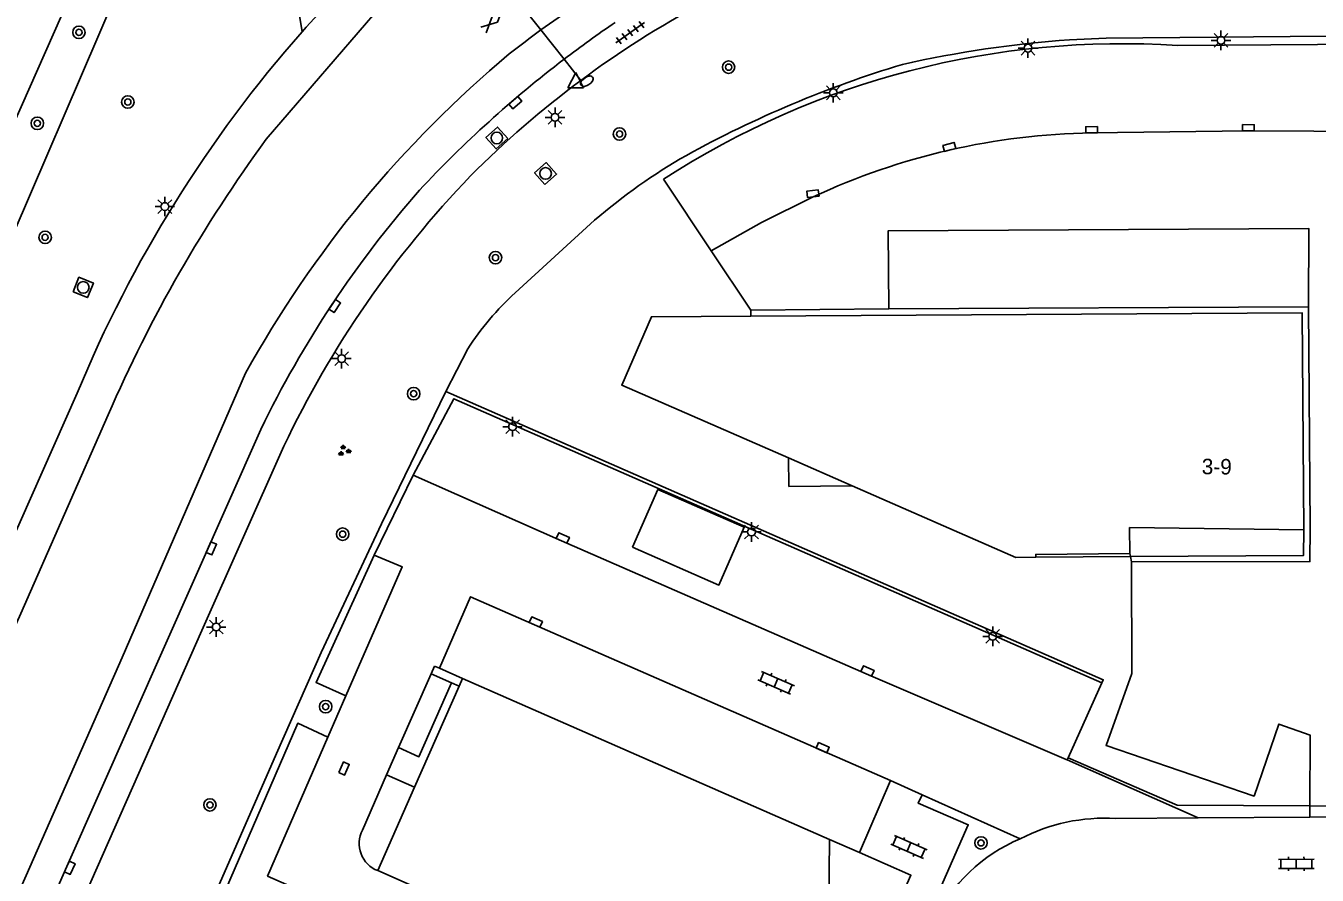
# Model space of a CAD drawing. Extents: x 131000 to 133013, y 393000 to 396501.
# Drawn here: x 131810.6 to 131893.7, y 394917.7 to 394972.4 of the extents above; entities that cross this region are included whole.
import ezdxf

# ---------------------------------------------------------------- set-up
doc = ezdxf.new("R2010")
doc.units = 0
for name, color, linetype in [('gg-afsc-hekwerk', 7, 'Continuous'), ('gg-afsc-muur', 7, 'Continuous'), ('gg-anno-huisnummerreeks BGT', 7, 'Continuous'), ('gg-bbg-hoofdgebouw', 7, 'Continuous'), ('gg-bbg-onder overbouw', 7, 'Continuous'), ('gg-bbg-pand overbouw', 7, 'Continuous'), ('gg-knt-verharding', 7, 'Continuous'), ('gg-knt-verharding nz', 7, 'Continuous'), ('gt-grn-groengrens', 7, 'Continuous'), ('gt-grn-vlakafsluiter', 7, 'Continuous'), ('gt-grn-weggrens', 7, 'Continuous'), ('gt-symb-boom', 7, 'Continuous'), ('gt-symb-brandkraan', 7, 'Continuous'), ('gt-symb-gesloten verharding', 7, 'Continuous'), ('gt-symb-groenvak', 7, 'Continuous'), ('gt-symb-klinker verharding', 7, 'Continuous'), ('gt-symb-kolk', 7, 'Continuous'), ('gt-symb-kolk center center', 7, 'Continuous'), ('gt-symb-lichtmast', 7, 'Continuous'), ('gt-symb-rioolschacht', 7, 'Continuous'), ('gt-symb-tegel verharding', 7, 'Continuous'), ('gt-symb-waterafsluiter', 7, 'Continuous')]:
    doc.layers.add(name, color=color, linetype=linetype)

# ---------------------------------------------------------------- blocks, each defined once
blk = doc.blocks.new('gt0-LMAST')
at = {"layer": 'gt-symb-lichtmast'}
for p, q in [((-0.182, 0.173), (-0.447, 0.438)), ((-0.005, 0.246), (-0.005, 0.621)), ((0.172, 0.173), (0.437, 0.438)), ((-0.255, -0.004), (-0.63, -0.004)), ((-0.182, -0.181), (-0.447, -0.446)), ((-0.005, -0.254), (-0.005, -0.629)), ((0.437, -0.446), (0.172, -0.181)), ((0.245, -0.004), (0.62, -0.004))]:
    blk.add_line(p, q, dxfattribs=at)
blk.add_circle((-0.005, -0.004), 0.25, dxfattribs=at)
blk = doc.blocks.new('gt0-TEG1')
at = {"layer": 'gt-symb-tegel verharding'}
for p, q in [((-1.125, 0), (1.125, 0)), ((-0.9, -0.25), (-0.9, 0.25)), ((-0.45, -0.25), (-0.45, 0.25)), ((0, -0.25), (0, 0.25)), ((0.45, -0.25), (0.45, 0.25)), ((0.9, -0.25), (0.9, 0.25))]:
    blk.add_line(p, q, dxfattribs=at)
blk = doc.blocks.new('gt0-BOOM')
at = {"layer": 'gt-symb-boom'}
for radius in [0.4, 0.2]:
    blk.add_circle((0, 0), radius, dxfattribs=at)
blk = doc.blocks.new('gt0-GESVH1')
at = {"layer": 'gt-symb-gesloten verharding'}
for p, q in [((-0.992, -0.261), (0.008, 0.239)), ((0.008, -0.261), (-0.992, 0.239)), ((0.008, 0.239), (1.008, -0.261)), ((1.008, 0.239), (0.008, -0.261))]:
    blk.add_line(p, q, dxfattribs=at)
blk = doc.blocks.new('gt0-KOLK')
at = {"layer": 'gt-symb-kolk'}
blk.add_lwpolyline([(0, 0), (0.375, 0), (0.375, 0.4), (-0.375, 0.4), (-0.375, 0), (0, 0)], dxfattribs=at)
blk = doc.blocks.new('gt0-RS')
at = {"layer": 'gt-symb-rioolschacht'}
blk.add_lwpolyline([(-0.5, -0.5), (0.5, -0.5), (0.5, 0.5), (-0.5, 0.5)], close=True, dxfattribs=at)
blk.add_circle((0, 0), 0.375, dxfattribs=at)
blk = doc.blocks.new('gt0-WAFSL')
at = {"layer": 'gt-symb-waterafsluiter'}
for p, q in [((-0.5, -0.333), (0, 0.667)), ((0, 0.667), (0.5, -0.333)), ((0.5, -0.333), (-0.5, -0.333))]:
    blk.add_line(p, q, dxfattribs=at)
blk = doc.blocks.new('gt0-BR')
at = {"layer": 'gt-symb-brandkraan'}
for centre, radius, start, end in [((-0.244, 0), 0.206, 107.56694, 252.43307), ((0.599, -2.664), 3, 106.89205, 107.56694), ((0, -0.691), 0.938, 73.10799, 106.89205), ((-0.599, -2.664), 3, 72.43309, 73.10799), ((0.244, 0), 0.206, 287.56695, 72.43309), ((0.599, 2.664), 3, 252.43307, 253.10797), ((0, 0.691), 0.938, 253.10797, 286.89206), ((-0.599, 2.664), 3, 286.89206, 287.56695)]:
    blk.add_arc(centre, radius, start, end, dxfattribs=at)
blk = doc.blocks.new('gt0-KL1')
at = {"layer": 'gt-symb-klinker verharding'}
for p, q in [((-1.15, 0.3), (1.15, 0.3)), ((-1, -0.3), (-1, 0.3)), ((-0.5, 0.3), (-0.5, 0.45)), ((0, -0.3), (0, 0.3)), ((0.5, 0.3), (0.5, 0.45)), ((1, -0.3), (1, 0.3)), ((-1.15, -0.3), (1.15, -0.3)), ((-0.5, -0.45), (-0.5, -0.3)), ((0.5, -0.45), (0.5, -0.3))]:
    blk.add_line(p, q, dxfattribs=at)
blk = doc.blocks.new('gt0-KOLKCC')
at = {"layer": 'gt-symb-kolk center center'}
blk.add_lwpolyline([(-0.375, 0.2), (0.375, 0.2), (0.375, -0.2), (-0.375, -0.2)], close=True, dxfattribs=at)
blk = doc.blocks.new('gt0-GRVAK')
at = {"layer": 'gt-symb-groenvak'}
for p, q in [((-0.11, 0.189), (-0.228, 0.24)), ((-0.182, 0.153), (0.088, 0.153)), ((-0.091, 0.211), (-0.156, 0.322)), ((-0.047, 0.214), (-0.047, 0.393)), ((-0.004, 0.211), (0.061, 0.322)), ((0.015, 0.189), (0.133, 0.24)), ((0.262, -0.052), (0.197, 0.059)), ((0.305, -0.049), (0.305, 0.13)), ((0.349, -0.052), (0.414, 0.059)), ((-0.245, -0.228), (-0.363, -0.177)), ((-0.318, -0.264), (-0.047, -0.264)), ((-0.226, -0.206), (-0.291, -0.095)), ((-0.183, -0.203), (-0.183, -0.024)), ((-0.139, -0.206), (-0.074, -0.095)), ((-0.12, -0.228), (-0.002, -0.177)), ((0.243, -0.074), (0.125, -0.023)), ((0.17, -0.11), (0.441, -0.11)), ((0.368, -0.074), (0.486, -0.023))]:
    blk.add_line(p, q, dxfattribs=at)

msp = doc.modelspace()

# ---------------------------------------------------------------- linework, layer by layer
at = {"layer": 'gg-afsc-hekwerk'}
for p, q in [((131847.171, 394959.864), (131842.065, 394955.195)), ((131837.604, 394948.848), (131839.008, 394951.577)), ((131877.655, 394925.264), (131879.819, 394930.082)), ((131897.868, 394922.132), (131893.202, 394922.16))]:
    msp.add_line(p, q, dxfattribs=at)
for points in [[(131903.78, 394971.81), (131880.092, 394971.597), (131877.743, 394971.48)], [(131837.604, 394948.848), (131833.448, 394940.313), (131829.566, 394932.029), (131826.705, 394925.539), (131822.874, 394916.809), (131823.026, 394916.543), (131808.751, 394884.954)], [(131879.819, 394930.082), (131879.911, 394930.286), (131837.604, 394948.848)], [(131849.604, 394938.812), (131855.169, 394936.378), (131856.799, 394940.103), (131851.234, 394942.538), (131849.604, 394938.812)], [(131893.202, 394922.16), (131884.654, 394922.21), (131877.655, 394925.264)]]:
    msp.add_lwpolyline(points, dxfattribs=at)
for centre, radius, start, end in [((131882.837, 394899.326), 72.333, 94.03832, 102.66003), ((131888.123, 394900.29), 72.75, 106.89239, 118.79886), ((131872.109, 394930.875), 38.239, 119.84825, 130.70416), ((131854.361, 394941.705), 18.253, 132.34914, 147.25913)]:
    msp.add_arc(centre, radius, start, end, dxfattribs=at)
at = {"layer": 'gg-afsc-muur'}
for p, q in [((131836.871, 394931.161), (131836.663, 394930.652)), ((131836.871, 394931.161), (131837.183, 394931.021)), ((131836.663, 394930.652), (131837.956, 394930.086)), ((131837.183, 394931.021), (131838.663, 394930.355)), ((131837.956, 394930.086), (131838.449, 394929.87))]:
    msp.add_line(p, q, dxfattribs=at)
at = {"layer": 'gg-bbg-hoofdgebouw'}
for p, q in [((131838.663, 394930.355), (131838.449, 394929.87)), ((131862.294, 394919.995), (131838.663, 394930.355)), ((131838.449, 394929.87), (131835.587, 394923.372)), ((131835.587, 394923.372), (131833.218, 394917.992)), ((131833.218, 394917.992), (131862.333, 394905.215))]:
    msp.add_line(p, q, dxfattribs=at)
for points in [[(131859.642, 394944.561), (131848.918, 394949.254), (131850.831, 394953.657), (131857.228, 394953.694)], [(131857.228, 394953.694), (131892.715, 394953.902), (131892.805, 394939.932)], [(131875.561, 394938.173), (131874.27, 394938.162), (131863.746, 394942.765)]]:
    msp.add_lwpolyline(points, dxfattribs=at)
at = {"layer": 'gg-bbg-onder overbouw'}
for p, q in [((131863.746, 394942.765), (131859.642, 394944.561)), ((131862.294, 394919.995), (131862.202, 394911.141))]:
    msp.add_line(p, q, dxfattribs=at)
for points in [[(131892.805, 394939.932), (131881.603, 394940.075), (131881.608, 394938.408)], [(131881.608, 394938.408), (131875.564, 394938.354), (131875.561, 394938.173)]]:
    msp.add_lwpolyline(points, dxfattribs=at)
at = {"layer": 'gg-bbg-pand overbouw'}
for p, q in [((131875.561, 394938.173), (131881.653, 394938.212)), ((131864.216, 394919.152), (131862.294, 394919.995))]:
    msp.add_line(p, q, dxfattribs=at)
for points in [[(131863.746, 394942.765), (131859.674, 394942.729), (131859.642, 394944.561)], [(131881.653, 394938.212), (131892.798, 394938.284), (131892.805, 394939.932)], [(131864.425, 394910.635), (131867.527, 394917.7), (131864.216, 394919.152)]]:
    msp.add_lwpolyline(points, dxfattribs=at)
at = {"layer": 'gg-knt-verharding'}
for p, q in [((131799.343, 394942.554), (131817.322, 394983.075)), ((131854.668, 394957.892), (131851.612, 394962.513)), ((131857.226, 394954.082), (131854.668, 394957.892)), ((131866.109, 394954.16), (131857.226, 394954.082)), ((131893.12, 394954.298), (131866.109, 394954.16)), ((131807.785, 394935.011), (131813.879, 394948.731)), ((131835.501, 394943.451), (131832.99, 394938.313)), ((131881.731, 394937.878), (131881.653, 394938.212)), ((131836.663, 394930.652), (131834.552, 394925.922)), ((131831.156, 394929.252), (131830.009, 394926.589)), ((131833.789, 394924.162), (131834.552, 394925.922)), ((131877.589, 394925.117), (131877.509, 394925.153)), ((131877.655, 394925.264), (131877.589, 394925.117)), ((131886.023, 394921.383), (131877.589, 394925.117)), ((131833.789, 394924.162), (131832.23, 394920.606)), ((131835.587, 394923.372), (131833.789, 394924.162)), ((131866.208, 394923.79), (131864.216, 394919.152)), ((131868.253, 394922.879), (131866.208, 394923.79)), ((131874.568, 394920.037), (131868.253, 394922.879)), ((131893.202, 394922.16), (131893.198, 394921.433)), ((131886.023, 394921.383), (131880.706, 394921.348)), ((131893.198, 394921.433), (131886.023, 394921.383)), ((131893.198, 394921.433), (131897.888, 394921.481))]:
    msp.add_line(p, q, dxfattribs=at)
for points in [[(131825.488, 394979.091), (131827.72, 394975.961), (131828.353, 394972.005)], [(131884.697, 394971.113), (131902.679, 394971.249), (131902.848, 394923.577), (131897.824, 394923.515)], [(131881.731, 394937.878), (131893.206, 394937.891), (131893.222, 394940.062), (131893.12, 394954.298)], [(131879.819, 394930.082), (131838.116, 394948.372), (131835.501, 394943.451)], [(131825.69, 394946.403), (131813.219, 394918.254), (131800.285, 394888.961), (131791.639, 394869.234), (131782.976, 394849.54), (131781.85, 394846.843)], [(131811.436, 394909.735), (131821.907, 394933.452), (131827.18, 394945.316)], [(131832.99, 394938.313), (131829.246, 394930.11), (131831.156, 394929.252)], [(131881.731, 394937.878), (131881.74, 394930.685), (131880.089, 394926.038), (131889.612, 394922.796), (131891.202, 394927.422), (131893.229, 394926.707), (131893.202, 394922.16)], [(131834.552, 394925.922), (131835.871, 394925.326), (131837.956, 394930.086)], [(131830.009, 394926.589), (131828.074, 394927.478), (131823.42, 394916.74), (131826.985, 394915.22), (131862.405, 394899.633)], [(131868.253, 394922.879), (131868.004, 394922.331), (131871.215, 394920.946), (131867.57, 394912.629), (131868.052, 394912.425)]]:
    msp.add_lwpolyline(points, dxfattribs=at)
for centre, radius, start, end in [((131877.006, 394928.516), 65.256, 127.50922, 138.20768), ((131883.562, 394918.66), 62.537, 109.66743, 126.59253), ((131890.633, 394917.136), 83.002, 138.61956, 157.62584), ((131890.439, 394910.916), 74.592, 124.20639, 127.32793), ((131881.107, 394916.983), 54.249, 86.20588, 122.93574), ((131890.234, 394911.222), 74.225, 127.34568, 137.05194), ((131883.618, 394918.602), 62.616, 126.60182, 135.20174), ((131886.981, 394916.911), 66.205, 136.21437, 154.59274), ((131887.586, 394916.411), 68.78, 138.71327, 154.14747), ((131879.989, 394909.678), 11.692, 86.48652, 117.62649), ((131833.898, 394919.743), 1.878, 152.63393, 248.77573), ((131878.498, 394910.436), 10.374, 112.26164, 155.71264)]:
    msp.add_arc(centre, radius, start, end, dxfattribs=at)
at = {"layer": 'gg-knt-verharding nz'}
msp.add_line((131881.653, 394938.212), (131881.608, 394938.408), dxfattribs=at)
for points in [[(131826.046, 394965.08), (131833.434, 394973.659), (131839.019, 394978.069)], [(131897.824, 394923.515), (131897.683, 394965.579), (131889.241, 394965.618), (131879.155, 394965.49)], [(131861.243, 394961.374), (131857.912, 394959.715), (131854.668, 394957.892)], [(131866.109, 394954.16), (131866.066, 394959.189), (131893.131, 394959.344), (131893.12, 394954.298)], [(131780.795, 394850.018), (131782.267, 394853.403), (131816.767, 394931.714), (131824.71, 394950.01)], [(131815.875, 394947.336), (131810.244, 394934.536), (131808.945, 394931.623), (131770.367, 394843.592), (131767.437, 394837.1)], [(131835.501, 394943.451), (131845.047, 394939.229), (131864.65, 394930.667), (131877.509, 394925.153)], [(131831.156, 394929.252), (131834.791, 394937.543), (131832.99, 394938.313)], [(131866.208, 394923.79), (131839.187, 394935.625), (131837.183, 394931.021)], [(131863.19, 394901.369), (131826.128, 394917.644), (131830.009, 394926.589)]]:
    msp.add_lwpolyline(points, dxfattribs=at)
for centre, radius, start, end in [((131883.725, 394917.197), 67.944, 89.86947, 126.07174), ((131884.168, 394916.637), 68.657, 126.09472, 128.22789), ((131888.222, 394914.867), 72.587, 129.87794, 151.04306), ((131879.843, 394921.464), 44.031, 90.89511, 114.98757), ((131899.831, 394910.999), 91.483, 143.76024, 156.59641)]:
    msp.add_arc(centre, radius, start, end, dxfattribs=at)
at = {"layer": 'gt-grn-groengrens'}
msp.add_line((131800.809, 394938.166), (131819.562, 394981.824), dxfattribs=at)
at = {"layer": 'gt-grn-vlakafsluiter'}
msp.add_line((131857.228, 394953.694), (131857.226, 394954.082), dxfattribs=at)
at = {"layer": 'gt-grn-weggrens'}
for p, q in [((131839.019, 394978.069), (131843.72, 394972.115)), ((131843.72, 394972.115), (131845.208, 394970.23)), ((131845.208, 394970.23), (131846.283, 394968.87))]:
    msp.add_line(p, q, dxfattribs=at)

# ---------------------------------------------------------------- block references
at = {"layer": 'gt-symb-boom'}
for p in [(131813.987, 394971.962), (131855.796, 394969.719), (131817.133, 394967.475), (131811.307, 394966.105), (131848.777, 394965.417), (131811.812, 394958.764), (131840.795, 394957.458), (131835.525, 394948.698), (131830.957, 394939.653), (131829.862, 394928.55), (131822.417, 394922.224), (131872.036, 394919.778)]:
    msp.add_blockref('gt0-BOOM', p, dxfattribs=at)
at = {"layer": 'gt-symb-brandkraan', "rotation": -145.80135638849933}
msp.add_blockref('gt0-BR', (131846.673, 394968.815), dxfattribs=at)
at = {"layer": 'gt-symb-gesloten verharding', "rotation": 43.298645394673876}
msp.add_blockref('gt0-GESVH1', (131840.73, 394972.804), dxfattribs=at)
at = {"layer": 'gt-symb-groenvak'}
msp.add_blockref('gt0-GRVAK', (131831.04, 394945.022), dxfattribs=at)
at = {"layer": 'gt-symb-klinker verharding'}
for p, rotation in [((131858.854, 394930.085), -23.642501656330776), ((131867.402, 394919.519), -23.642501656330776), ((131892.327, 394918.428), -179.54164354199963)]:
    msp.add_blockref('gt0-KL1', p, dxfattribs=dict(at, rotation=rotation))
at = {"layer": 'gt-symb-kolk'}
for p, rotation in [((131841.938, 394967.585), -139.38006045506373), ((131879.155, 394965.49), 0.2864765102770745), ((131889.241, 394965.618), -0.2864765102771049), ((131870.047, 394964.392), 14.772723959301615), ((131861.243, 394961.374), 6.60603415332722), ((131830.284, 394954.452), -123.57881372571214), ((131845.047, 394939.229), -23.82289949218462), ((131822.33, 394938.827), -113.8984778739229), ((131843.306, 394933.812), -23.642501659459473), ((131864.65, 394930.667), -23.694971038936), ((131861.773, 394925.721), -23.514556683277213), ((131813.219, 394918.254), -113.89847787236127)]:
    msp.add_blockref('gt0-KOLK', p, dxfattribs=dict(at, rotation=rotation))
at = {"layer": 'gt-symb-kolk center center', "rotation": 66.66595872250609}
msp.add_blockref('gt0-KOLKCC', (131831.051, 394924.566), dxfattribs=at)
at = {"layer": 'gt-symb-lichtmast'}
for p in [(131887.488, 394971.45), (131875.067, 394970.949), (131862.538, 394968.073), (131844.63, 394966.494), (131819.52, 394960.749), (131830.897, 394950.958), (131841.898, 394946.578), (131857.274, 394939.798), (131822.829, 394933.679), (131872.795, 394933.08)]:
    msp.add_blockref('gt0-LMAST', p, dxfattribs=at)
at = {"layer": 'gt-symb-rioolschacht'}
for p, rotation in [((131840.881, 394965.162), 131.88080981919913), ((131844.019, 394962.877), 41.35293636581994), ((131814.263, 394955.542), -22.077941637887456)]:
    msp.add_blockref('gt0-RS', p, dxfattribs=dict(at, rotation=rotation))
at = {"layer": 'gt-symb-tegel verharding', "rotation": 35.5176978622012}
msp.add_blockref('gt0-TEG1', (131849.462, 394971.942), dxfattribs=at)
at = {"layer": 'gt-symb-waterafsluiter'}
msp.add_blockref('gt0-WAFSL', (131845.954, 394968.713), dxfattribs=at)

# ---------------------------------------------------------------- texts
at = {"layer": 'gg-anno-huisnummerreeks BGT'}
msp.add_text('3-9', height=1, rotation=359.3, dxfattribs=at).set_placement((131886.24, 394943.515))

doc.saveas('drawing.dxf')
